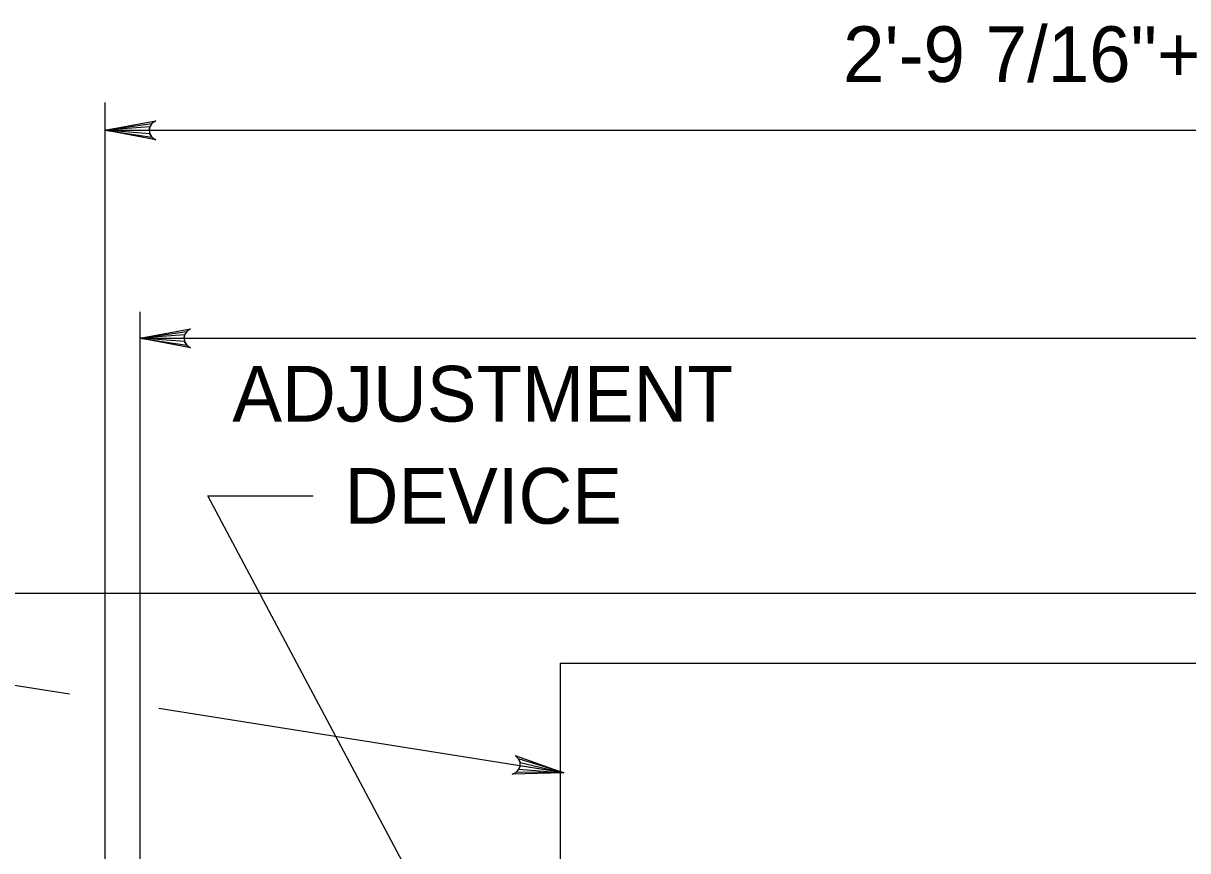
# Model space of a CAD drawing. Extents: x -0.3 to 6.9, y -6.5 to 3.5.
# Drawn here: x 1.361 to 2.615, y 2.461 to 3.352 of the extents above; entities that cross this region are included whole.
import ezdxf

# ---------------------------------------------------------------- set-up
doc = ezdxf.new("R2010")
doc.units = 0
for name, color, linetype in [('DETL-DIMS', 7, 'Continuous'), ('DETL-LINE', 7, 'Continuous'), ('DETL-NOTE', 7, 'Continuous')]:
    doc.layers.add(name, color=color, linetype=linetype)

msp = doc.modelspace()

# ---------------------------------------------------------------- linework, layer by layer
at = {"layer": 'DETL-DIMS'}
for p, q in [((1.4487, 3.2671), (1.4487, 2.3028)), ((1.4487, 3.2371), (4.4228, 3.2371)), ((1.4863, 3.0414), (1.4863, 2.3028)), ((1.4863, 3.013), (4.3851, 3.013)), ((1.8362, 2.3234), (1.5596, 2.8433)), ((1.5596, 2.8433), (1.6732, 2.8433)), ((1.4107, 2.6296), (1.1996, 2.6632)), ((1.9432, 2.5448), (1.5068, 2.6143))]:
    msp.add_line(p, q, dxfattribs=at)
for points in [[(1.4487, 3.2371), (1.5035, 3.2474), (1.4993, 3.2445), (1.4971, 3.2408), (1.4965, 3.2371), (1.4971, 3.2334), (1.4993, 3.2297), (1.5035, 3.2268), (1.4487, 3.2371), (1.4993, 3.2297), (1.4971, 3.2334), (1.4487, 3.2371), (1.4965, 3.2371), (1.4971, 3.2408), (1.4487, 3.2371), (1.4993, 3.2445)], [(1.4487, 3.2371), (1.5035, 3.2474), (1.4993, 3.2445), (1.4971, 3.2408), (1.4965, 3.2371), (1.4971, 3.2334), (1.4993, 3.2297), (1.5035, 3.2268), (1.4487, 3.2371), (1.4993, 3.2297), (1.4971, 3.2334), (1.4487, 3.2371), (1.4965, 3.2371), (1.4971, 3.2408), (1.4487, 3.2371), (1.4993, 3.2445)], [(1.4863, 3.013), (1.5411, 3.0233), (1.5369, 3.0204), (1.5347, 3.0167), (1.5341, 3.013), (1.5347, 3.0094), (1.5369, 3.0057), (1.5411, 3.0028), (1.4863, 3.013), (1.5369, 3.0057), (1.5347, 3.0094), (1.4863, 3.013), (1.5341, 3.013), (1.5347, 3.0167), (1.4863, 3.013), (1.5369, 3.0204)], [(1.4863, 3.013), (1.5411, 3.0233), (1.5369, 3.0204), (1.5347, 3.0167), (1.5341, 3.013), (1.5347, 3.0094), (1.5369, 3.0057), (1.5411, 3.0028), (1.4863, 3.013), (1.5369, 3.0057), (1.5347, 3.0094), (1.4863, 3.013), (1.5341, 3.013), (1.5347, 3.0167), (1.4863, 3.013), (1.5369, 3.0204)], [(1.9432, 2.5448), (1.8875, 2.5433), (1.8921, 2.5455), (1.8948, 2.5488), (1.896, 2.5524), (1.896, 2.5561), (1.8944, 2.5601), (1.8907, 2.5636), (1.9432, 2.5448), (1.8944, 2.5601), (1.896, 2.5561), (1.9432, 2.5448), (1.896, 2.5524), (1.8948, 2.5488), (1.9432, 2.5448), (1.8921, 2.5455)]]:
    msp.add_lwpolyline(points, dxfattribs=at)
at = {"layer": 'DETL-LINE'}
for p, q in [((4.7992, 2.7381), (1.0722, 2.7381)), ((1.9397, 2.2487), (1.9397, 2.6632)), ((1.9397, 2.6632), (3.9258, 2.6632))]:
    msp.add_line(p, q, dxfattribs=at)

# ---------------------------------------------------------------- texts
at = {"layer": 'DETL-NOTE'}
for s, p in [('2\'-9 7/16"+', (2.2441, 3.2891)), ('ADJUSTMENT', (1.5861, 2.9233)), ('DEVICE', (1.7071, 2.8133))]:
    msp.add_text(s, height=0.06, dxfattribs=at).set_placement(p)

doc.saveas('drawing.dxf')
